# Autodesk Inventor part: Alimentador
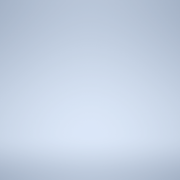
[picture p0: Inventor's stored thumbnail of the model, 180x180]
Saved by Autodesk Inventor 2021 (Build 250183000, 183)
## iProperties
Created: 2021-02
Part Number: Alimentador
Material: Genérico
Document SubType Name: Modeling
Designer: ATOUZA
Density: 1 g/cm^3
Appearance: Valor por defecto
Author: ATOUZA
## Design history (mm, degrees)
sketch "Boceto1"
  geometry: L1 (20, 20)-(-20, 20); L2 (-20, 20)-(-20, -20); L3 (-20, -20)-(20, -20); L4 (20, -20)-(20, 20); L5 (20, 20)-(-20, -20); L6 (-20, 20)-(20, -20); L7 (18, 18)-(-18, 18); L8 (-18, 18)-(-18, -18); L9 (-18, -18)-(18, -18); L10 (18, -18)-(18, 18); 1 further point
  constraints: 20 end point, 4 parallel, 2 midpoint, 2 perpendicular, 1 horizontal, 3 other
  dimensions: "d0" = 40 distance of L3.end L2.end; "d1" = 40 distance of L2.end L1.end; "d2" = 2 distance between parallel lines of L4 L10
extrude "Extrusión1" new body sketch "Boceto1" distance "d3" = 350; taper "d4" = 0 deg
sketch "Boceto2"
  geometry: L1 (2, 0)-(2, 350) reference; L2 (38, 0)-(38, 350) reference; L3 (2, 0)-(38, 0); L4 (38, 0)-(38, 38); L5 (38, 38)-(2, 38); L6 (2, 38)-(2, 0); 3 further points
  constraints: 8 end point, 2 parallel, 1 horizontal, 1 perpendicular, 1 point on line
  dimensions: "d5" = 38 distance of L4.end L3.end
extrude "Extrusión2" cut sketch "Boceto2" extent not by distance; stored distance "d6" = 0; taper "d7" = 0 deg
sketch "Boceto3"
  geometry: L1 (20, 0)-(20, 35); L2 (20, 35)-(20, 70); L3 (20, 105)-(20, 140); L4 (20, 140)-(20, 175); L5 (20, 175)-(20, 210); L6 (20, 210)-(20, 245); L7 (20, 245)-(20, 280); L8 (20, 280)-(20, 315); L9 (20, 280)-(20, 315); L10 (20, 175)-(20, 105); L11 (10, 175)-(10, 105); L12 (30, 105)-(30, 175); L13 (20, 315)-(20, 245); L14 (10, 315)-(10, 245); L15 (30, 245)-(30, 315); A1 r 10 centre (20, 175) between (30, 175) and (10, 175); A2 r 10 centre (20, 105) between (10, 105) and (30, 105); A3 r 10 centre (20, 315) between (30, 315) and (10, 315); A4 r 10 centre (20, 245) between (10, 245) and (30, 245)
  constraints: 34 end point, 8 point on circle, 8 tangent, 5 point on line, 4 centre point, 2 collinear, 2 midpoint, 2 parallel, 1 vertical
  dimensions: "d8" = 35 distance of L1.start L1.end; "d9" = 35 distance of L2.end L1.end; "d10" = 35 distance of L3.start L3.end; "d11" = 35 distance of L3.end L4.end; "d12" = 35 distance of L4.end L5.end; "d13" = 35 distance of L5.end L6.end; "d14" = 35 distance of L6.end L7.end; "d15" = 35 distance of L7.end L8.end; "d16" = 35 distance of L9.start L9.end; "d17" = 20 diameter of A2; "d18" = 20 diameter of A4; "d21" = 35 distance of L3.start L2.end
extrude "Extrusión3" cut sketch "Boceto3" extent not by distance; stored distance "d19" = 0; taper "d20" = 0 deg
sketch "Boceto4"
  geometry: L1 (-20, 0)-(-20, 35); L2 (-20, 35)-(-20, 70); C1 r 10 at (-20, 52.5)
  constraints: 4 end point, 1 centre point, 1 midpoint, 1 point on line, 1 vertical
  dimensions: "d22" = 35 distance of L1.start L1.end; "d23" = 35 distance of L1.end L2.end; "d24" = 20 diameter of C1
extrude "Extrusión4" cut sketch "Boceto4" distance "d25" = 4; taper "d26" = 0 deg
node "Sólido1"
